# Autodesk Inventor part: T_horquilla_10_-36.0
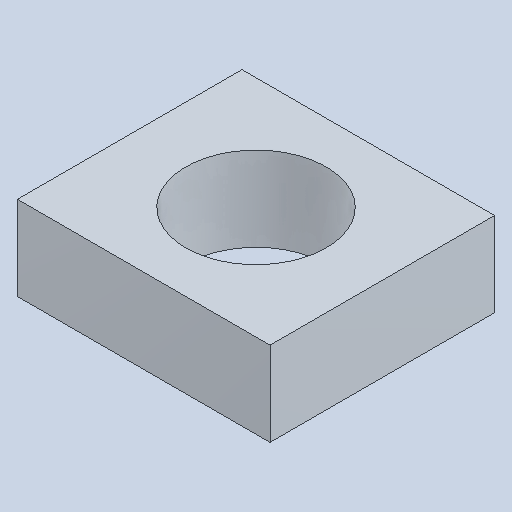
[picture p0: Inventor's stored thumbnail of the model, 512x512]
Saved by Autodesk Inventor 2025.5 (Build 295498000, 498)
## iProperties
Created: 2026-10
Part Number: T_horquilla_10_-36.0
Material: Genérico
Document SubType Name: Modeling
Designer: Luis M
Density: 1 g/cm^3
Appearance: Valor por defecto
Author: Luis M
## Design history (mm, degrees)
feature "Base1"
node "Sólido1"
